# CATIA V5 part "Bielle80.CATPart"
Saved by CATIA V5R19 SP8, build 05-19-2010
Part number: Bielle80
Publications: "Demi_longueur_bielle", "Rayon_bielle", "Diam_trou_ext", "Diam_trou_int", "Hauteur_Extremite"
Bounding box of the stored display mesh (mm): x -60 to 60, y -20 to 20, z -10 to 10
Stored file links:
  F:\! CONCEPTION\PROJET\Mécanisme 590\CAO\Bielle80.CATPart
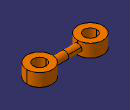
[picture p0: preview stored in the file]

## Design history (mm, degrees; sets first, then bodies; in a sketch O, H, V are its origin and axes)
Parameters
  Demi_longueur_bielle = 40 mm
  Rayon_bielle = 6 mm
  Diam_trou_ext = 40 mm
  Diam_trou_int = 20 mm {= Diam_trou_ext /2}
  Hauteur_Extremite = 10 mm
Body1 (main body)
  Sketch1 on xy-plane, origin (0, 0, 0), H (1, 0, 0), V (0, 1, 0)
    point P1 (-40, 0)
    line L1 (-40, 0) -> (-40, 6)
    line L2 (-40, 6) -> (0, 6)
    line L3 (0, 6) -> (0, 0)
    line L4 (0, 0) -> (-40, 0)
    length L2 = 40 {= Demi_longueur_bielle}
    length L1 = 6 {= Rayon_bielle}
    coincidence: P1 H, L3 V
    vertical: L1 V, L3 V
    horizontal: L2 H, L4 H
  Shaft1: profile Sketch1, axis Sketch1.L4, angle 360
  Sketch2 on xy-plane, origin (0, 0, 0), H (1, 0, 0), V (0, 1, 0)
    circle A1 centre (-40, 0) radius 20
    point P1 (-40, 0)
    reference projected line E1 (-40, 10) -> (-40, -10) from edge [face of Shaft1 from Sketch1.L1 | face of Shaft1 from Sketch1.L2]
    radius A1 = 20 {= Diam_trou_ext /2}
    coincidence: P1 H, P1 E1
  Pad1: profile Sketch2, direction (0, 0, 1), length 10 {= Hauteur_Extremite}, mirrored extent
  Sketch3 on end face of Pad1, origin (0, 0, 10), H (1, 0, 0), V (0, 1, 0)
    circle A1 centre (-40, 0) radius 10
    point P1 (-40, 0)
    reference projected circle E1 centre (-40, 0) radius 20 from edge [face of Pad1 from Sketch2.A1 | end face of Pad1]
    radius A1 = 10 {= Diam_trou_int /2}
    coincidence: P1 H
    concentricity: A1 E1
  Pocket1: profile Sketch3, direction (0, 0, -1), through (limit type 6)
  Mirror1: of Shaft1, Sketch1, Pad1, Sketch2, Pocket1, Sketch3, about yz-plane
